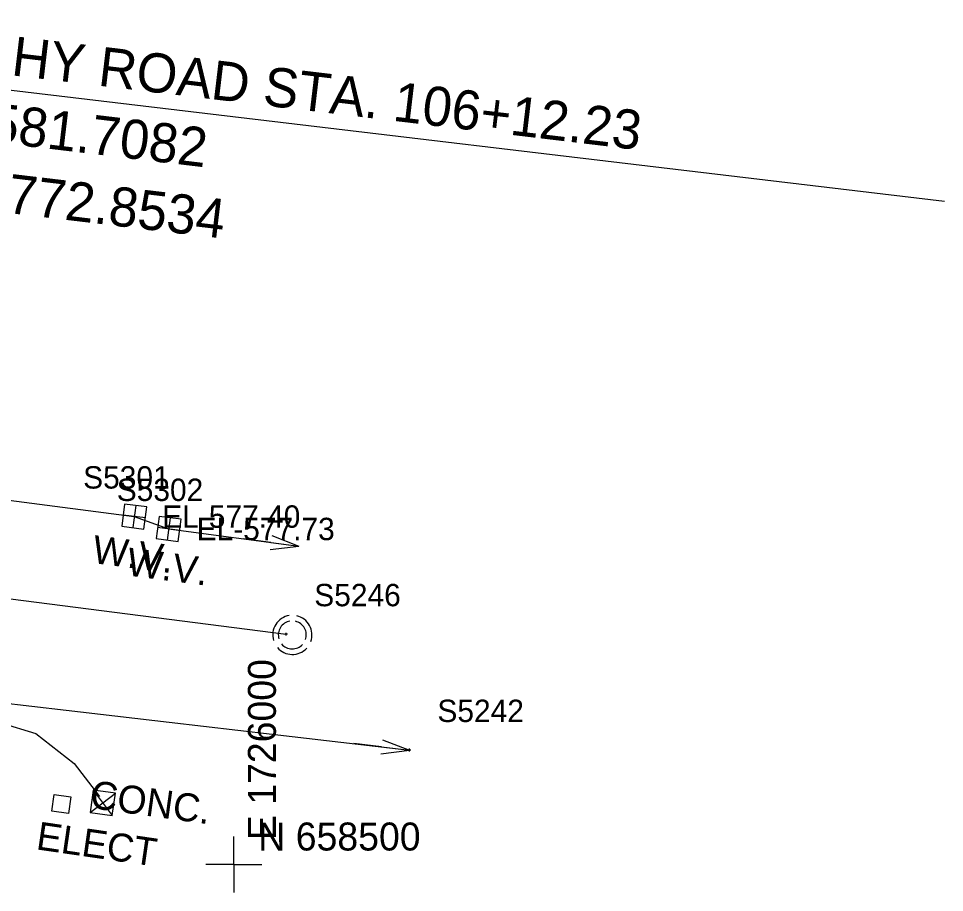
# Model space of a CAD drawing. Extents: x 1724534 to 1727318, y 657156 to 660047.
# Drawn here: x 1725961.5 to 1726127, y 658495 to 658651.2 of the extents above; entities that cross this region are included whole.
import ezdxf

# ---------------------------------------------------------------- set-up
doc = ezdxf.new("R2010")
doc.units = 0
for name, color, linetype in [('SURVEY - CENTERLINE - Preliminary Text', 7, 'Continuous'), ('SURVEY - CONTROL - Grid', 7, 'Continuous'), ('SURVEY - CONTROL - Grid Text', 7, 'Continuous'), ('SURVEY - DRAINAGE - Storm Sewer', 7, 'Continuous'), ('SURVEY - DRAINAGE - Storm Sewer - Points - Locators', 7, 'Continuous'), ('SURVEY - DRAINAGE - Storm Sewer - Points - Numbers', 7, 'Continuous'), ('SURVEY - PROPERTY - Property Markers with Text', 7, 'Continuous'), ('SURVEY - UTILITIES - Electric (Underground) with Text', 7, 'Continuous'), ('SURVEY - UTILITIES - Poles and Miscellaneous with Text', 7, 'Continuous'), ('SURVEY - UTILITIES - Water - Points - Elevations', 7, 'Continuous'), ('SURVEY - UTILITIES - Water - Points - Locators', 7, 'Continuous'), ('SURVEY - UTILITIES - Water - Points - Numbers', 7, 'Continuous'), ('SURVEY - UTILITIES - Water with Text', 7, 'Continuous')]:
    doc.layers.add(name, color=color, linetype=linetype)

msp = doc.modelspace()

# ---------------------------------------------------------------- linework, layer by layer
at = {"layer": 'SURVEY - CENTERLINE - Preliminary Text'}
msp.add_line((1725925.42, 658642.54), (1726126.99, 658618.52), dxfattribs=at)
at = {"layer": 'SURVEY - CONTROL - Grid'}
for q in [(1726000, 658505), (1725995, 658500), (1726005, 658500), (1726000, 658495)]:
    msp.add_line((1726000, 658500), q, dxfattribs=at)
at = {"layer": 'SURVEY - DRAINAGE - Storm Sewer'}
for p, q in [((1725900.58, 658555.13), (1726009.35, 658541.15)), ((1725877.56, 658538.29), (1726031.36, 658520.46)), ((1726026.39, 658521.03), (1726021.43, 658521.61)), ((1726026.54, 658522.27), (1726031.36, 658520.46)), ((1726026.25, 658519.79), (1726031.36, 658520.46)), ((1726026.39, 658521.03), (1726031.36, 658520.46)), ((1726026.39, 658521.03), (1726031.36, 658520.46))]:
    msp.add_line(p, q, dxfattribs=at)
for radius, start, end in [(3.5, 98.9594, 196.2542), (2.5, 99.7619, 196.2001), (2.5, 340.5504, 77.0954), (3.5, 340.5532, 76.9994), (3.5, 220.3962, 317.1893), (2.5, 220.3142, 317.1488)]:
    msp.add_arc((1726010.43, 658541.03), radius, start, end, dxfattribs=at)
at = {"layer": 'SURVEY - DRAINAGE - Storm Sewer - Points - Locators'}
for p, q in [((1726009.35, 658540.9), (1726009.35, 658541.4)), ((1726009.6, 658541.15), (1726009.1, 658541.15)), ((1726009.35, 658541.15), (1726009.35, 658541.15)), ((1726009.35, 658541.15), (1726009.35, 658541.15)), ((1726031.61, 658520.46), (1726031.11, 658520.46)), ((1726031.36, 658520.21), (1726031.36, 658520.71)), ((1726031.36, 658520.46), (1726031.36, 658520.46)), ((1726031.36, 658520.46), (1726031.36, 658520.46))]:
    msp.add_line(p, q, dxfattribs=at)
at = {"layer": 'SURVEY - PROPERTY - Property Markers with Text'}
msp.add_lwpolyline([(1725967.47, 658509.53), (1725967.88, 658512.5), (1725970.85, 658512.09), (1725970.44, 658509.12)], close=True, dxfattribs=at)
at = {"layer": 'SURVEY - UTILITIES - Electric (Underground) with Text'}
msp.add_lwpolyline([(1725780.97, 658547.45), (1725837.59, 658541.08), (1725892.76, 658533.99), (1725944.68, 658527.23), (1725958.36, 658525.3), (1725964.57, 658523.41), (1725971.45, 658518.07), (1725975.98, 658512.13)], dxfattribs=at)
at = {"layer": 'SURVEY - UTILITIES - Poles and Miscellaneous with Text'}
for p, q in [((1725974.85, 658513.26), (1725978.26, 658508.75)), ((1725974.3, 658509.3), (1725978.81, 658512.72)), ((1725976.55, 658511.01), (1725976.55, 658511.01))]:
    msp.add_line(p, q, dxfattribs=at)
msp.add_lwpolyline([(1725974.85, 658513.26), (1725974.3, 658509.3), (1725978.26, 658508.75), (1725978.81, 658512.72), (1725974.85, 658513.26)], dxfattribs=at)
at = {"layer": 'SURVEY - UTILITIES - Water - Points - Locators'}
for p, q in [((1725982.44, 658564.17), (1725981.93, 658560.2)), ((1725984.17, 658561.93), (1725980.2, 658562.44)), ((1725988.59, 658561.95), (1725988.08, 658557.98)), ((1725990.32, 658559.71), (1725986.35, 658560.22))]:
    msp.add_line(p, q, dxfattribs=at)
at = {"layer": 'SURVEY - UTILITIES - Water with Text'}
for p, q in [((1725982.18, 658562.18), (1725982.18, 658562.18)), ((1725988.33, 658559.96), (1725988.33, 658559.96)), ((1726006.61, 658557.54), (1726001.66, 658558.2)), ((1726006.78, 658558.78), (1726011.57, 658556.88)), ((1726006.45, 658556.3), (1726011.57, 658556.88)), ((1726006.61, 658557.54), (1726011.57, 658556.88)), ((1726006.61, 658557.54), (1726011.57, 658556.88))]:
    msp.add_line(p, q, dxfattribs=at)
for points in [[(1725847.72, 658579.71), (1725982.18, 658562.18), (1725988.33, 658559.96), (1726011.57, 658556.88)], [(1725980.46, 658564.42), (1725979.94, 658560.46), (1725983.91, 658559.94), (1725984.42, 658563.91), (1725980.46, 658564.42)], [(1725986.61, 658562.2), (1725986.1, 658558.24), (1725990.06, 658557.72), (1725990.57, 658561.69), (1725986.61, 658562.2)]]:
    msp.add_lwpolyline(points, dxfattribs=at)

# ---------------------------------------------------------------- texts
at = {"layer": 'SURVEY - CENTERLINE - Preliminary Text'}
for s, p in [('MURPHY ROAD STA. 106+12.23', (1725932.68, 658644.32)), ('N 658581.7082', (1725931.23, 658632.16)), ('E 1725772.8534', (1725929.78, 658619.99))]:
    msp.add_text(s, height=7, rotation=353.2033, dxfattribs=at).set_placement(p)
at = {"layer": 'SURVEY - CONTROL - Grid Text'}
msp.add_text(' E 1726000 ', height=5, rotation=90, dxfattribs=at).set_placement((1726007.5, 658502.5))
msp.add_text(' N 658500 ', height=5, dxfattribs=at).set_placement((1726002.5, 658502.5))
at = {"layer": 'SURVEY - DRAINAGE - Storm Sewer - Points - Numbers'}
for s, p in [('S5246', (1726014.35, 658546.15)), ('S5242', (1726036.36, 658525.46))]:
    msp.add_text(s, height=4, dxfattribs=at).set_placement(p)
at = {"layer": 'SURVEY - PROPERTY - Property Markers with Text'}
msp.add_text('CONC.', height=5, rotation=352.13, dxfattribs=at).set_placement((1725974.11, 658510.13))
at = {"layer": 'SURVEY - UTILITIES - Poles and Miscellaneous with Text'}
msp.add_text('ELECT', height=5, rotation=351.7546, dxfattribs=at).set_placement((1725964.49, 658502.73))
at = {"layer": 'SURVEY - UTILITIES - Water - Points - Elevations'}
for s, p in [('EL-577.40', (1725987.18, 658560.18)), ('EL-577.73', (1725993.33, 658557.96))]:
    msp.add_text(s, height=4, dxfattribs=at).set_placement(p)
at = {"layer": 'SURVEY - UTILITIES - Water - Points - Numbers'}
for s, p in [('S5301', (1725973.05, 658567.18)), ('S5302', (1725979.05, 658564.96))]:
    msp.add_text(s, height=4, dxfattribs=at).set_placement(p)
at = {"layer": 'SURVEY - UTILITIES - Water with Text'}
for p in [(1725974.51, 658553.9), (1725980.66, 658551.68)]:
    msp.add_text('W.V.', height=5, rotation=352.6575, dxfattribs=at).set_placement(p)

doc.saveas('drawing.dxf')
